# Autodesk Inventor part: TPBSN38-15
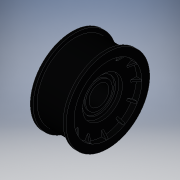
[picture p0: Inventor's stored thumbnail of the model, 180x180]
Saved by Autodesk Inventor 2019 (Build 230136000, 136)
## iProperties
Created: 2022-11
Part Number: TPBSN38-15
Material: Generic
Catalog Web Link: www.cadenas.de
Description: TPBSN,TPCFN-Idlers
Vendor: MISUMI
Document SubType Name: Modeling
Designer: psAdmin
Manufacturer: MISUMI
Mass: 14.3884 g
Surface Area: 66.5133 cm^2
Volume: 14.3884 cm^3
Density: 1 g/cm^3
Appearance: PSOLRGB-61-63-66
Category: PARTsolutions
Company: MISUMI
Title: TPBSN38-15
Author: Cadenas PARTsolutions
Comments: Idlers
PSOL_IDENT_0: {$CADENAS_DATA/23d-libs/misumi/metric/51_timing_pulleys/tpbsn.prj},167 {VTYP=3D},{NB=TPBSN38-15},{LI
PSOL_IDENT_1: NA=TPBSN38-15},{NN=TPBSN,TPCFN},{DATE=30.06.2021 13:25:47},{GEOMDATE=19.03.2015 00:00:00},{VERSION=}
PSOL_IDENT_2: ,{LINEID=10},{WBVAR=TS},{WBNUMERIC=}  {NB=TPBSN38-15},{LINA=TPBSN38-15},{KT=DUMMY},{PN=TPBSN38-15},{
PSOL_IDENT_3: TS=TPBSN},{MAT=Glass Reinforced Nylon},{OT=80 degree or Less},{TYPE=TPBSN},{D=38},{W=15},{W01=15},{W
PSOL_IDENT_4: 1=0},{W11=18},{F=42},{F1=42},{L=18},{L1=18},{S=4.5},{BN=6200ZZ},{DD=10},{B=9},{AID=WS010S},{TSA='TPB
PSOL_IDENT_5: SN','Flanged Idler','TPCFN','Flat Idler'}
NB: TPBSN38-15
NN: TPBSN,TPCFN
NT: Idlers
NBSYN: $PN.
LINA: TPBSN38-15
CATALOG: Misumi
PN: TPBSN38-15
TS: Flanged Idler
MAT: Glass Reinforced Nylon
OT: 80 degree or Less
D: 38
W: 15
W1: 0
F: 42
L: 18
S: 4.5
BN: 6200ZZ
DD: 10
B: 9
AID: WS010S
SUPPLIER: MISUMI
ARTICLENO: TPBSN38-15
BOMINFO: TPBSN38-15
CREATOR: CADENAS GmbH
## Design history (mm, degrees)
sketch "Sketch_1"
  geometry: L1 (18, 0)-(0, 0); L2 (0, 17)-(2.7, 17); L3 (2.7, 17)-(2.7, 10); L4 (2.7, 10)-(4.5, 10); L5 (4.5, 10)-(4.5, 8.333); L6 (4.5, 8.333)-(5.25, 8.333); L7 (5.25, 8.333)-(5.25, 6.667); L8 (5.25, 6.667)-(4.5, 6.667); L9 (4.5, 6.667)-(4.5, 5); L10 (4.5, 5)-(13.5, 5); L11 (13.5, 5)-(13.5, 6.667); L12 (13.5, 6.667)-(12.75, 6.667); L13 (12.75, 6.667)-(12.75, 8.333); L14 (12.75, 8.333)-(13.5, 8.333); L15 (13.5, 8.333)-(13.5, 10); L16 (13.5, 10)-(15.3, 10); L17 (15.3, 10)-(15.3, 17); L18 (15.3, 17)-(18, 17); L19 (18, 17)-(18, 21); L20 (18, 21)-(16.5, 21); L21 (16.5, 21)-(16.5, 19); L22 (16.5, 19)-(1.5, 19); L23 (1.5, 19)-(1.5, 21); L24 (1.5, 21)-(0, 21); L25 (0, 21)-(0, 17)
  constraints: 50 end point
revolve "Revolution1" sketch "Sketch_1" stored, may be unused: angle "d0" = 360 deg
sketch "Sketch_3"
  geometry: L1 (0.5, 14.2)-(-0.5, 14.2); L2 (-0.5, 14.2)-(-0.5, 18); L3 (-0.5, 18)-(0.5, 18); L4 (0.5, 18)-(0.5, 14.2); L5 (0.5, 14.2)-(-0.5, 14.2)
  constraints: 10 end point
revolve "Revolution2" sketch "Sketch_3" stored, may be unused: angle "d1" = 40 deg
pattern_circular "Circular Pattern1" dims angle "d3" = 30 deg
sketch "Sketch_5"
  geometry: L1 (0.5, 14.2)-(-0.5, 14.2); L2 (-0.5, 14.2)-(-0.5, 18); L3 (-0.5, 18)-(0.5, 18); L4 (0.5, 18)-(0.5, 14.2); L5 (0.5, 14.2)-(-0.5, 14.2)
  constraints: 10 end point
revolve "Revolution3" sketch "Sketch_5" stored, may be unused: angle "d5" = 40 deg
pattern_circular "Circular Pattern2" dims angle "d7" = 30 deg
body "Solid1"
